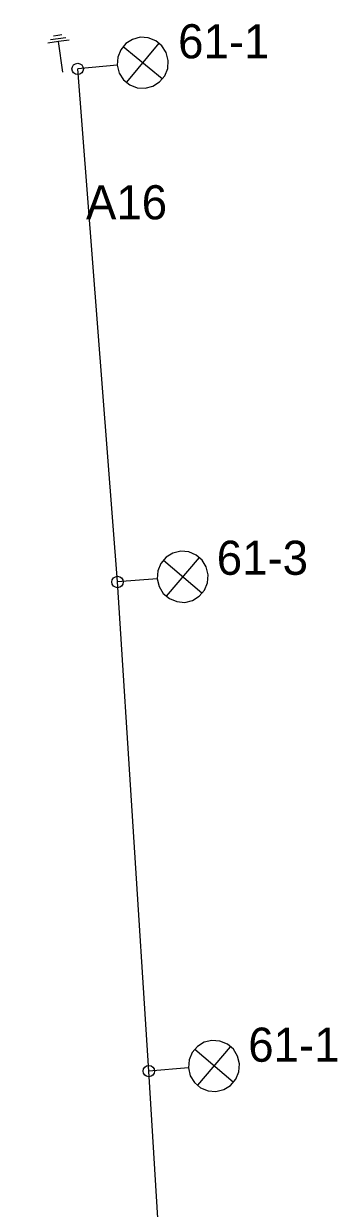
# Model space of a CAD drawing. Extents: x 25497851 to 25498523, y 6686544 to 6687372.
# Drawn here: x 25498469.5 to 25498497.1, y 6687256.4 to 6687360.6 of the extents above; entities that cross this region are included whole.
import ezdxf

# ---------------------------------------------------------------- set-up
doc = ezdxf.new("R2010")
doc.units = 0
for name, color, linetype in [('EL_CABLE_ILMA', 7, 'Continuous'), ('KEYGWT_ANNOTATION', 7, 'Continuous'), ('Level 17', 7, 'Continuous'), ('Level 63', 7, 'Continuous'), ('Taso 1', 7, 'Continuous')]:
    doc.layers.add(name, color=color, linetype=linetype)

msp = doc.modelspace()

# ---------------------------------------------------------------- linework, layer by layer
at = {"layer": 'EL_CABLE_ILMA'}
msp.add_lwpolyline([(25498469.54, 6687179.13), (25498482.11, 6687190.14), (25498483.15, 6687225.9), (25498480.55, 6687268.5), (25498477.8, 6687311.51), (25498474.29, 6687356.63)], dxfattribs=at)
at = {"layer": 'Level 17'}
for points in [[(25498471.91, 6687359.21), (25498472.58, 6687359.31)], [(25498472.54, 6687359.57), (25498472.17, 6687359.52)], [(25498472.91, 6687359.62), (25498472.54, 6687359.57)], [(25498472.58, 6687359.31), (25498473.24, 6687359.4)], [(25498472.6, 6687359.06), (25498473.54, 6687359.19)], [(25498471.67, 6687358.92), (25498472.6, 6687359.06)], [(25498472.99, 6687356.35), (25498472.61, 6687359.05)]]:
    msp.add_lwpolyline(points, dxfattribs=at)
at = {"layer": 'Taso 1'}
for p, q in [((25498481.73, 6687355.75), (25498478.3, 6687358.58)), ((25498481.43, 6687358.88), (25498478.6, 6687355.45)), ((25498477.77, 6687356.95), (25498474.29, 6687356.63)), ((25498485.22, 6687310.52), (25498481.84, 6687313.41)), ((25498484.98, 6687313.65), (25498482.09, 6687310.27)), ((25498481.29, 6687311.79), (25498477.8, 6687311.51)), ((25498487.72, 6687270.64), (25498484.84, 6687267.27)), ((25498487.97, 6687267.51), (25498484.59, 6687270.4)), ((25498484.04, 6687268.78), (25498480.55, 6687268.5))]:
    msp.add_line(p, q, dxfattribs=at)
for points in [[(25498482.25, 6687357.38), (25498482.08, 6687358.06), (25498481.7, 6687358.65), (25498481.16, 6687359.1), (25498480.5, 6687359.36), (25498479.8, 6687359.41), (25498479.12, 6687359.23), (25498478.53, 6687358.85), (25498478.08, 6687358.31), (25498477.82, 6687357.66), (25498477.77, 6687356.95), (25498477.95, 6687356.27), (25498478.33, 6687355.68), (25498478.87, 6687355.23), (25498479.52, 6687354.97), (25498480.23, 6687354.93), (25498480.91, 6687355.1), (25498481.5, 6687355.48), (25498481.95, 6687356.02), (25498482.21, 6687356.68)], [(25498485.78, 6687312.14), (25498485.61, 6687312.83), (25498485.24, 6687313.43), (25498484.71, 6687313.88), (25498484.06, 6687314.15), (25498483.36, 6687314.21), (25498482.67, 6687314.04), (25498482.07, 6687313.68), (25498481.62, 6687313.14), (25498481.35, 6687312.49), (25498481.29, 6687311.79), (25498481.46, 6687311.1), (25498481.82, 6687310.5), (25498482.36, 6687310.05), (25498483.01, 6687309.78), (25498483.71, 6687309.72), (25498484.39, 6687309.89), (25498484.99, 6687310.25), (25498485.45, 6687310.79), (25498485.72, 6687311.44)], [(25498488.52, 6687269.13), (25498488.36, 6687269.82), (25498487.99, 6687270.42), (25498487.46, 6687270.87), (25498486.81, 6687271.14), (25498486.1, 6687271.2), (25498485.42, 6687271.03), (25498484.82, 6687270.67), (25498484.36, 6687270.13), (25498484.09, 6687269.48), (25498484.04, 6687268.78), (25498484.2, 6687268.09), (25498484.57, 6687267.49), (25498485.11, 6687267.04), (25498485.76, 6687266.77), (25498486.46, 6687266.71), (25498487.14, 6687266.88), (25498487.74, 6687267.24), (25498488.2, 6687267.78), (25498488.47, 6687268.43)]]:
    msp.add_lwpolyline(points, close=True, dxfattribs=at)
for centre in [(25498474.29, 6687356.63), (25498477.8, 6687311.51), (25498480.55, 6687268.5)]:
    msp.add_circle(centre, 0.5, dxfattribs=at)

# ---------------------------------------------------------------- texts
at = {"layer": 'KEYGWT_ANNOTATION'}
for s, p in [('61-1', (25498483.13, 6687357.56)), ('A16', (25498475.02, 6687343.4)), ('61-3', (25498486.53, 6687312.14)), ('61-1', (25498489.3, 6687269.32))]:
    msp.add_text(s, height=3, dxfattribs=at).set_placement(p)
at = {"layer": 'Level 63'}
msp.add_text('(C) KEYPRO 2000', height=0.0001, rotation=188.1, dxfattribs=at).set_placement((25498472.91, 6687359.62))

doc.saveas('drawing.dxf')
